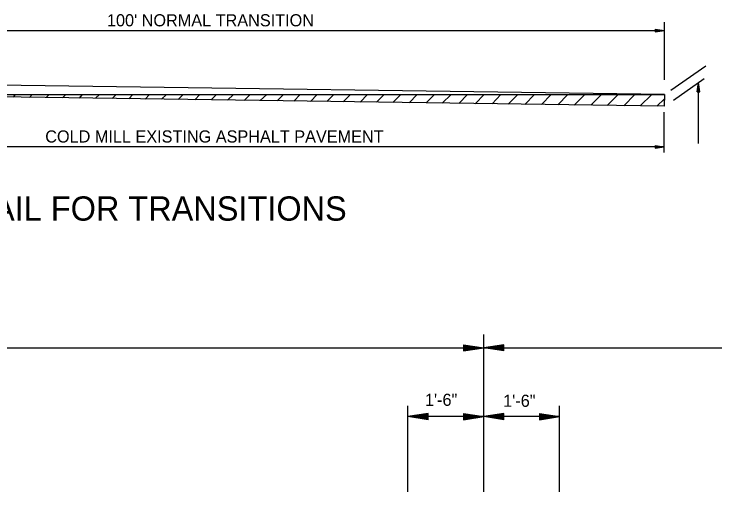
# Model space of a CAD drawing. Extents: x -2842 to 2681, y -2139 to 474.
# Drawn here: x -379 to -32.6, y -1483.8 to -1247.6 of the extents above; entities that cross this region are included whole.
import ezdxf

# ---------------------------------------------------------------- set-up
doc = ezdxf.new("R2010")
doc.units = 0
doc.layers.add('Default', color=7, linetype='Continuous')

msp = doc.modelspace()

# ---------------------------------------------------------------- linework, layer by layer
at = {"layer": 'Default'}
for p, q in [((-57.55, -1280.1), (-57.55, -1251.68)), ((-469.11, -1255.67), (-57.55, -1255.67)), ((-62.22, -1255), (-57.55, -1255.67)), ((-62.22, -1255), (-62.22, -1256.33)), ((-62.22, -1255.22), (-59.1, -1255.67)), ((-62.22, -1255.22), (-58.45, -1255.67)), ((-62.22, -1255.44), (-60.67, -1255.67)), ((-62.22, -1255.44), (-59.99, -1255.67)), ((-62.22, -1256.33), (-57.55, -1255.67)), ((-62.22, -1255.88), (-60.67, -1255.67)), ((-62.22, -1256.11), (-59.1, -1255.67)), ((-62.22, -1256.33), (-58.45, -1255.67)), ((-62.22, -1256.11), (-59.99, -1255.67)), ((-62.22, -1255.88), (-61.55, -1255.67)), ((-62.22, -1255.67), (-61.55, -1255.67)), ((-54.44, -1285.2), (-37.13, -1273.21)), ((-53.11, -1290.09), (-38.01, -1279.44)), ((-41.34, -1286.09), (-40.68, -1281.42)), ((-40.68, -1311.64), (-40.68, -1281.42)), ((-40.01, -1286.09), (-40.68, -1281.42)), ((-57.55, -1287.42), (-469.11, -1281.66)), ((-41.11, -1286.09), (-40.68, -1282.09)), ((-41.11, -1286.09), (-40.68, -1282.99)), ((-40.91, -1286.09), (-40.68, -1283.65)), ((-40.91, -1286.09), (-40.68, -1284.55)), ((-40.01, -1286.09), (-40.68, -1282.09)), ((-40.23, -1286.09), (-40.68, -1282.99)), ((-40.23, -1286.09), (-40.68, -1283.65)), ((-40.46, -1286.09), (-40.68, -1284.55)), ((-584.58, -1287.43), (-57.54, -1287.43)), ((-57.78, -1293.21), (-469.11, -1287.42)), ((-379.31, -1288.69), (-378.26, -1287.42)), ((-371.41, -1288.8), (-370.04, -1287.42)), ((-363.08, -1288.92), (-361.61, -1287.42)), ((-354.99, -1289.03), (-353.37, -1287.42)), ((-346.68, -1289.15), (-345.16, -1287.42)), ((-338.79, -1289.25), (-336.72, -1287.42)), ((-330.45, -1289.37), (-328.51, -1287.42)), ((-322.34, -1289.49), (-320.29, -1287.42)), ((-314.24, -1289.61), (-312.06, -1287.44)), ((-306.14, -1289.72), (-303.64, -1287.42)), ((-297.82, -1289.83), (-295.42, -1287.42)), ((-289.72, -1289.95), (-287.2, -1287.42)), ((-281.61, -1290.06), (-278.99, -1287.42)), ((-273.52, -1290.17), (-270.55, -1287.42)), ((-265.19, -1290.29), (-262.33, -1287.42)), ((-257.32, -1290.4), (-254.11, -1287.42)), ((-248.98, -1290.52), (-245.89, -1287.42)), ((-240.66, -1290.63), (-237.67, -1287.42)), ((-232.56, -1290.75), (-229.24, -1287.42)), ((-224.45, -1290.87), (-221.02, -1287.42)), ((-216.34, -1290.97), (-212.8, -1287.42)), ((-208.01, -1291.09), (-204.35, -1287.42)), ((-199.91, -1291.21), (-196.14, -1287.42)), ((-191.81, -1291.32), (-187.92, -1287.42)), ((-183.71, -1291.44), (-179.71, -1287.42)), ((-175.39, -1291.56), (-171.27, -1287.42)), ((-167.5, -1291.66), (-163.05, -1287.42)), ((-159.18, -1291.78), (-154.83, -1287.42)), ((-151.07, -1291.9), (-146.62, -1287.42)), ((-142.76, -1292.01), (-138.39, -1287.42)), ((-134.88, -1292.13), (-129.95, -1287.42)), ((-126.56, -1292.24), (-121.74, -1287.42)), ((-118.4, -1292.31), (-113.52, -1287.42)), ((-110.34, -1292.47), (-105.3, -1287.42)), ((-102.24, -1292.58), (-96.86, -1287.42)), ((-93.92, -1292.7), (-88.65, -1287.42)), ((-85.81, -1292.81), (-80.42, -1287.42)), ((-77.7, -1292.93), (-72.22, -1287.42)), ((-69.61, -1293.04), (-63.77, -1287.42)), ((-57.55, -1287.42), (-57.78, -1293.21)), ((-41.34, -1286.09), (-40.01, -1286.09)), ((-40.46, -1286.09), (-40.68, -1285.2)), ((-40.68, -1286.09), (-40.68, -1285.2)), ((-61.28, -1293.16), (-57.63, -1289.52)), ((-57.78, -1316.08), (-57.78, -1296.1)), ((-62.22, -1312.53), (-57.78, -1313.19)), ((-62.22, -1312.53), (-58.45, -1313.19)), ((-62.22, -1312.53), (-62.22, -1313.86)), ((-62.22, -1312.74), (-59.33, -1313.19)), ((-62.22, -1312.74), (-59.99, -1313.19)), ((-57.78, -1313.19), (-469.11, -1313.19)), ((-62.22, -1312.98), (-60.88, -1313.19)), ((-62.22, -1312.98), (-61.55, -1313.19)), ((-62.22, -1313.86), (-57.78, -1313.19)), ((-62.22, -1313.41), (-60.88, -1313.19)), ((-62.22, -1313.63), (-59.33, -1313.19)), ((-62.22, -1313.63), (-58.45, -1313.19)), ((-62.22, -1313.41), (-59.99, -1313.19)), ((-62.22, -1313.19), (-61.55, -1313.19)), ((-146.9, -1483.79), (-146.9, -1405.99)), ((-646.87, -1412.6), (-146.9, -1412.6)), ((-156.88, -1411.11), (-146.89, -1412.61)), ((-156.88, -1411.11), (-156.88, -1414.11)), ((-156.88, -1411.36), (-148.56, -1412.61)), ((-156.88, -1411.61), (-150.29, -1412.61)), ((-156.88, -1411.86), (-151.94, -1412.61)), ((-156.88, -1412.11), (-153.64, -1412.61)), ((-156.88, -1412.36), (-155.31, -1412.61)), ((-156.88, -1414.11), (-146.89, -1412.61)), ((-156.88, -1413.08), (-153.64, -1412.61)), ((-156.88, -1413.61), (-150.29, -1412.61)), ((-156.88, -1413.86), (-148.56, -1412.61)), ((-156.88, -1413.36), (-151.94, -1412.61)), ((-156.88, -1412.83), (-155.31, -1412.61)), ((-146.9, -1412.6), (265.57, -1412.6)), ((-136.89, -1411.11), (-146.89, -1412.61)), ((-136.89, -1414.11), (-146.89, -1412.61)), ((-136.89, -1411.36), (-145.21, -1412.61)), ((-136.89, -1413.86), (-145.21, -1412.61)), ((-136.89, -1411.61), (-143.51, -1412.61)), ((-136.89, -1413.61), (-143.51, -1412.61)), ((-136.89, -1411.86), (-141.84, -1412.61)), ((-136.89, -1413.36), (-141.84, -1412.61)), ((-136.89, -1412.11), (-140.14, -1412.61)), ((-136.89, -1413.08), (-140.14, -1412.61)), ((-136.89, -1412.36), (-138.46, -1412.61)), ((-136.89, -1412.83), (-138.46, -1412.61)), ((-136.89, -1414.11), (-136.89, -1411.11)), ((-184.4, -1483.79), (-184.4, -1441.16)), ((-109.4, -1483.79), (-109.4, -1441.16)), ((-146.9, -1446.55), (-184.4, -1446.55)), ((-174.38, -1445.06), (-184.38, -1446.56)), ((-174.38, -1448.06), (-184.38, -1446.56)), ((-174.38, -1445.31), (-182.71, -1446.56)), ((-174.38, -1447.81), (-182.71, -1446.56)), ((-174.38, -1445.56), (-181.01, -1446.56)), ((-174.38, -1447.56), (-181.01, -1446.56)), ((-174.38, -1445.81), (-179.33, -1446.56)), ((-174.38, -1447.31), (-179.33, -1446.56)), ((-174.38, -1446.06), (-177.63, -1446.56)), ((-174.38, -1447.03), (-177.63, -1446.56)), ((-174.38, -1446.31), (-175.96, -1446.56)), ((-174.38, -1446.78), (-175.96, -1446.56)), ((-174.38, -1448.06), (-174.38, -1445.06)), ((-156.88, -1445.06), (-146.89, -1446.56)), ((-156.88, -1445.06), (-156.88, -1448.06)), ((-156.88, -1445.31), (-148.56, -1446.56)), ((-156.88, -1445.56), (-150.29, -1446.56)), ((-156.88, -1445.81), (-151.94, -1446.56)), ((-156.88, -1446.06), (-153.64, -1446.56)), ((-156.88, -1446.31), (-155.31, -1446.56)), ((-156.88, -1448.06), (-146.89, -1446.56)), ((-156.88, -1447.03), (-153.64, -1446.56)), ((-156.88, -1447.56), (-150.29, -1446.56)), ((-156.88, -1447.81), (-148.56, -1446.56)), ((-156.88, -1447.31), (-151.94, -1446.56)), ((-156.88, -1446.78), (-155.31, -1446.56)), ((-109.4, -1446.55), (-146.9, -1446.55)), ((-136.89, -1445.06), (-146.89, -1446.56)), ((-136.89, -1448.06), (-146.89, -1446.56)), ((-136.89, -1445.31), (-145.21, -1446.56)), ((-136.89, -1447.81), (-145.21, -1446.56)), ((-136.89, -1445.56), (-143.51, -1446.56)), ((-136.89, -1447.56), (-143.51, -1446.56)), ((-136.89, -1445.81), (-141.84, -1446.56)), ((-136.89, -1447.31), (-141.84, -1446.56)), ((-136.89, -1446.06), (-140.14, -1446.56)), ((-136.89, -1447.03), (-140.14, -1446.56)), ((-136.89, -1446.31), (-138.46, -1446.56)), ((-136.89, -1446.78), (-138.46, -1446.56)), ((-136.89, -1448.06), (-136.89, -1445.06)), ((-119.39, -1445.06), (-109.39, -1446.56)), ((-119.39, -1445.06), (-119.39, -1448.06)), ((-119.39, -1445.31), (-111.06, -1446.56)), ((-119.39, -1445.56), (-112.79, -1446.56)), ((-119.39, -1445.81), (-114.44, -1446.56)), ((-119.39, -1446.06), (-116.14, -1446.56)), ((-119.39, -1446.31), (-117.81, -1446.56)), ((-119.39, -1448.06), (-109.39, -1446.56)), ((-119.39, -1447.03), (-116.14, -1446.56)), ((-119.39, -1447.56), (-112.79, -1446.56)), ((-119.39, -1447.81), (-111.06, -1446.56)), ((-119.39, -1447.31), (-114.44, -1446.56)), ((-119.39, -1446.78), (-117.81, -1446.56))]:
    msp.add_line(p, q, dxfattribs=at)

# ---------------------------------------------------------------- texts
for s, height, p in [("100' NORMAL TRANSITION", 6, (-333.06, -1253.68)), ('COLD MILL EXISTING ASPHALT PAVEMENT', 6, (-363.56, -1311.1)), ('DETAIL FOR TRANSITIONS', 12, (-421.44, -1349.71)), ('1\'-6"', 6, (-175.93, -1441.23)), ('1\'-6"', 6, (-137.26, -1441.71))]:
    msp.add_text(s, height=height, dxfattribs=at).set_placement(p)

doc.saveas('drawing.dxf')
